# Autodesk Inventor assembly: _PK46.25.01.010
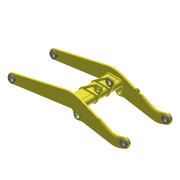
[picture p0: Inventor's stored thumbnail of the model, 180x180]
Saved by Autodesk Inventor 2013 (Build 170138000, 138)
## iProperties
Created: 2005-04
Part Number: _PK46.25.01.010
Document SubType Name: Assembly
Designer: salex
Manufacturer: Standard
Standards Organization: Custom
Author: salex
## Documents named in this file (8)
- C:\Product Design Suite 2013 Test Drive\Inventor Optimization\Workspace\_PK46.25.01.010.iam
- C:\Product Design Suite 2013 Test Drive\Inventor Optimization\Workspace\Assy, Chassis, Front\PK46.25.01.001.ipt
- C:\Product Design Suite 2013 Test Drive\Inventor Optimization\Workspace\Assy, Chassis, Front\PK46.25.01.002.ipt
- C:\Product Design Suite 2013 Test Drive\Inventor Optimization\Workspace\Assy, Chassis, Front\PK46.25.01.003.ipt
- C:\Product Design Suite 2013 Test Drive\Inventor Optimization\Workspace\Assy, Chassis, Front\PK46.25.01.004.ipt
- C:\Product Design Suite 2013 Test Drive\Inventor Optimization\Workspace\Assy, Chassis, Front\PK46.25.01.008.ipt
- C:\Product Design Suite 2013 Test Drive\Inventor Optimization\Workspace\Assy, Chassis, Front\PK46.25.01.012.ipt
- C:\Product Design Suite 2013 Test Drive\Inventor Optimization\Workspace\Assy, Chassis, Front\_PK46.25.01.020.iam
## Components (19 placed, 7 different names)
1. PK46.25.01.001:1 — Insert:3, Insert:4, Insert:7, Insert:8, Mate:1, Mate:2, Mate:3, Insert:10, Insert:11, Angle:1
2. PK46.25.01.002:1 — Insert:1, Insert:2, Insert:5, Insert:6, Mate:1, Mate:2, Mate:3, Insert:9, Insert:12, Angle:2, Mate:9, Mate:10
3. PK46.25.01.003:1 — Insert:3, Insert:14
4. PK46.25.01.003:2 — Insert:4, Insert:16
5. PK46.25.01.003:3 — Insert:1, Insert:13
6. PK46.25.01.003:4 — Insert:2, Insert:15
7. PK46.25.01.003:5 — Insert:5
8. PK46.25.01.003:6 — Insert:6
9. PK46.25.01.003:7 — Insert:7
10. PK46.25.01.003:8 — Insert:8
11. PK46.25.01.004:1 — Insert:10
12. PK46.25.01.004:2 — Insert:9
13. PK46.25.01.008:1 — Insert:11, Mate:6, Mate:7, Mate:8
14. PK46.25.01.008:2 — Insert:12, Mate:4, Mate:5
15. PK46.25.01.012:1 — Insert:15
16. PK46.25.01.012:2 — Insert:16, Angle:1
17. PK46.25.01.012:3 — Insert:13, Angle:2
18. PK46.25.01.012:4 — Insert:14
19. _PK46.25.01.020:1 [sub-assembly] — Mate:4, Mate:5, Mate:6, Mate:7, Mate:8, Mate:14, Flush:1, Flush:5, Angle:4, Mate:20, Mate:21
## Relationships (34: Insert 16, Mate 13, Angle 3, Flush 2)
- Insert:1: PK46.25.01.002:1 ↔ PK46.25.01.003:3
- Insert:2: PK46.25.01.002:1 ↔ PK46.25.01.003:4
- Insert:3: PK46.25.01.001:1 ↔ PK46.25.01.003:1
- Insert:4: PK46.25.01.001:1 ↔ PK46.25.01.003:2
- Insert:5: PK46.25.01.002:1 ↔ PK46.25.01.003:5
- Insert:6: PK46.25.01.002:1 ↔ PK46.25.01.003:6
- Insert:7: PK46.25.01.001:1 ↔ PK46.25.01.003:7
- Insert:8: PK46.25.01.001:1 ↔ PK46.25.01.003:8
- Mate:1: PK46.25.01.001:1 ↔ PK46.25.01.002:1
- Mate:2: PK46.25.01.001:1 ↔ PK46.25.01.002:1
- Mate:3: PK46.25.01.001:1 ↔ PK46.25.01.002:1
- Insert:9: PK46.25.01.002:1 ↔ PK46.25.01.004:2
- Insert:10: PK46.25.01.001:1 ↔ PK46.25.01.004:1
- Insert:11: PK46.25.01.001:1 ↔ PK46.25.01.008:1
- Insert:12: PK46.25.01.002:1 ↔ PK46.25.01.008:2
- Mate:4: PK46.25.01.008:2 ↔ _PK46.25.01.020:1
- Mate:5: PK46.25.01.008:2 ↔ _PK46.25.01.020:1
- Mate:6: PK46.25.01.008:1 ↔ _PK46.25.01.020:1
- Mate:7: PK46.25.01.008:1 ↔ _PK46.25.01.020:1
- Mate:8: PK46.25.01.008:1 ↔ _PK46.25.01.020:1
- Insert:13: PK46.25.01.003:3 ↔ PK46.25.01.012:3
- Insert:14: PK46.25.01.003:1 ↔ PK46.25.01.012:4
- Insert:15: PK46.25.01.003:4 ↔ PK46.25.01.012:1
- Insert:16: PK46.25.01.003:2 ↔ PK46.25.01.012:2
- Angle:1: PK46.25.01.001:1 ↔ PK46.25.01.012:2
- Angle:2: PK46.25.01.002:1 ↔ PK46.25.01.012:3
- Mate:9: PK46.25.01.002:1
- Mate:10: PK46.25.01.002:1
- Mate:14: _PK46.25.01.020:1
- Flush:1: _PK46.25.01.020:1
- Flush:5: _PK46.25.01.020:1
- Angle:4: _PK46.25.01.020:1
- Mate:20: _PK46.25.01.020:1
- Mate:21: _PK46.25.01.020:1
